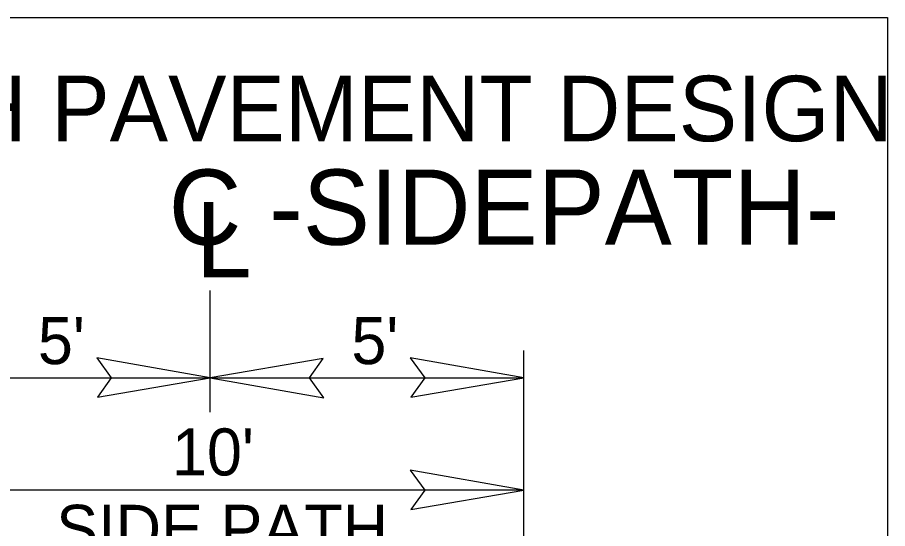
# Model space of a CAD drawing. Extents: x 1487909 to 1489267, y 497866 to 499814.
# Drawn here: x 1489135.48 to 1489149.36, y 498372.11 to 498380.27 of the extents above; entities that cross this region are included whole.
import ezdxf

# ---------------------------------------------------------------- set-up
doc = ezdxf.new("R2010")
doc.units = 0
for name, color, linetype in [('Default', 7, 'Continuous'), ('Prop Dimension', 7, 'Continuous'), ('Prop Dimension Text', 7, 'Continuous'), ('Prop Terminator CELL', 7, 'Continuous'), ('Sheet Typical CELL', 7, 'Continuous'), ('Typical Hinge Slope Interstate CELL', 7, 'Continuous')]:
    doc.layers.add(name, color=color, linetype=linetype)

msp = doc.modelspace()

# ---------------------------------------------------------------- linework, layer by layer
at = {"layer": 'Prop Dimension'}
for p, q in [((1489138.554, 498373.968), (1489138.554, 498375.909)), ((1489143.554, 498368.422), (1489143.554, 498374.955)), ((1489133.554, 498374.517), (1489138.554, 498374.517)), ((1489138.554, 498374.517), (1489143.554, 498374.517)), ((1489143.554, 498372.726), (1489133.554, 498372.726))]:
    msp.add_line(p, q, dxfattribs=at)
at = {"layer": 'Prop Terminator CELL'}
for points in [[(1489136.754, 498374.207), (1489138.554, 498374.517), (1489136.744, 498374.837), (1489136.974, 498374.517)], [(1489140.354, 498374.827), (1489138.554, 498374.517), (1489140.364, 498374.197), (1489140.134, 498374.517)], [(1489141.754, 498374.207), (1489143.554, 498374.517), (1489141.744, 498374.837), (1489141.974, 498374.517)], [(1489141.754, 498372.416), (1489143.554, 498372.726), (1489141.744, 498373.046), (1489141.974, 498372.726)]]:
    msp.add_lwpolyline(points, close=True, dxfattribs=at)
at = {"layer": 'Sheet Typical CELL'}
msp.add_lwpolyline([(1489127.752, 498380.266), (1489149.357, 498380.266), (1489149.357, 498359.36), (1489127.752, 498359.36)], close=True, dxfattribs=at)

# ---------------------------------------------------------------- texts
at = {"layer": 'Default'}
msp.add_text('SIDEPATH PAVEMENT DESIGN', height=1.04413, rotation=359.9999, dxfattribs=at).set_placement((1489128.647, 498378.291))
at = {"layer": 'Prop Dimension Text'}
for s, p in [("5'", (1489135.804, 498374.736)), ("5'", (1489140.804, 498374.736)), ("10'", (1489137.943, 498372.96)), ('SIDE PATH', (1489136.096, 498371.742))]:
    msp.add_text(s, height=0.75, dxfattribs=at).set_placement(p)
at = {"layer": 'Typical Hinge Slope Interstate CELL'}
for s, p in [('C -SIDEPATH-', (1489137.89, 498376.64)), ('L', (1489138.322, 498376.121))]:
    msp.add_text(s, height=1.2, dxfattribs=at).set_placement(p)

doc.saveas('drawing.dxf')
